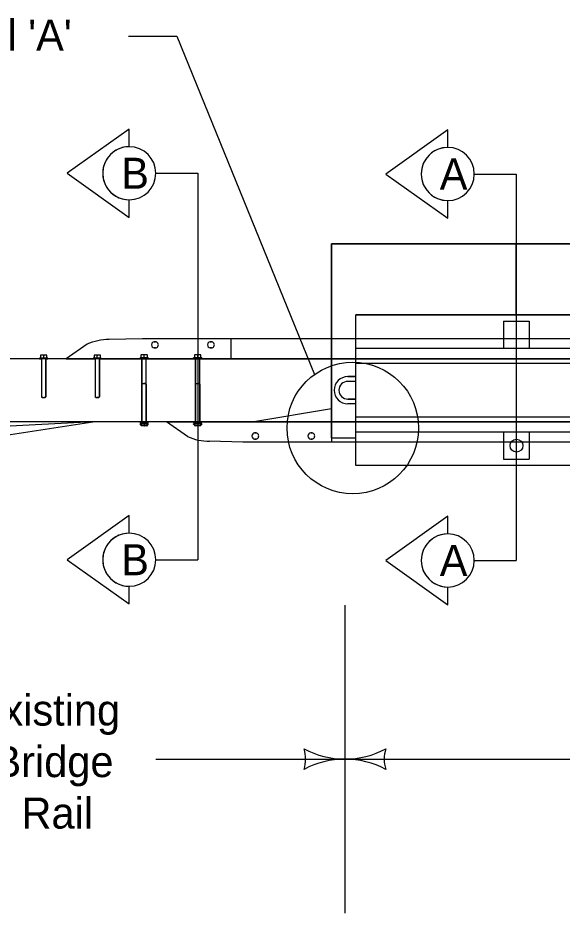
# Model space of a CAD drawing. Extents: x 10028 to 81668, y 3581 to 11018.
# Drawn here: x 21204 to 21470.5, y 8503.4 to 8941.5 of the extents above; entities that cross this region are included whole.
import ezdxf

# ---------------------------------------------------------------- set-up
doc = ezdxf.new("R2010")
doc.units = 0
for name, color, linetype in [('conPaving', 7, 'Continuous'), ('dsnCellsNorthArrow', 7, 'Continuous'), ('dsnTextTabulation', 7, 'Continuous'), ('Level 41', 7, 'Continuous'), ('Level 9', 7, 'Continuous')]:
    doc.layers.add(name, color=color, linetype=linetype)

msp = doc.modelspace()

# ---------------------------------------------------------------- linework, layer by layer
at = {"layer": 'conPaving'}
for p, q in [((21448.05, 8831.02), (21357.59, 8831.02)), ((21357.59, 8831.02), (21357.59, 8736.05)), ((21448.05, 8796.14), (21448.05, 8831.02)), ((21369.47, 8796.14), (21448.05, 8796.14)), ((21237.88, 8781.76), (21227.62, 8774.62)), ((21265.03, 8784.52), (21248.71, 8784.09)), ((21550.11, 8784.52), (21265.03, 8784.52)), ((21270.79, 8782.98), (21271.46, 8782.98)), ((21298.21, 8782.98), (21298.88, 8782.98)), ((21216.98, 8776.48), (21215.38, 8776.48)), ((21218, 8776.48), (21216.98, 8776.48)), ((21264.25, 8776.37), (21264.25, 8775.11)), ((21266.13, 8776.68), (21264.54, 8776.68)), ((21267.15, 8776.68), (21266.13, 8776.68)), ((21267.44, 8775.11), (21267.44, 8776.37)), ((21271.46, 8780.01), (21270.79, 8780.01)), ((21290.47, 8776.37), (21290.47, 8775.11)), ((21292.34, 8776.68), (21290.75, 8776.68)), ((21293.37, 8776.68), (21292.34, 8776.68)), ((21293.65, 8775.11), (21293.65, 8776.37)), ((21298.88, 8780.01), (21298.21, 8780.01)), ((21215.1, 8774.91), (21214.7, 8774.91)), ((21214.7, 8774.91), (21214.7, 8774.62)), ((21214.7, 8774.62), (21215.63, 8774.62)), ((21215.1, 8776.17), (21215.1, 8774.91)), ((21215.63, 8774.62), (21215.63, 8756.13)), ((21217.75, 8756.13), (21217.75, 8774.62)), ((21217.75, 8774.62), (21218.68, 8774.62)), ((21218.29, 8774.91), (21218.29, 8776.17)), ((21218.68, 8774.91), (21218.29, 8774.91)), ((21218.68, 8774.62), (21218.68, 8774.91)), ((21227.62, 8774.62), (21241.85, 8774.62)), ((21241.85, 8774.62), (21241.85, 8756.13)), ((21243.97, 8756.13), (21243.97, 8774.62)), ((21243.97, 8774.62), (21571.16, 8774.62)), ((21264.25, 8775.11), (21263.85, 8775.11)), ((21263.85, 8775.11), (21263.85, 8774.81)), ((21263.85, 8774.81), (21264.78, 8774.81)), ((21264.78, 8774.81), (21264.78, 8742.89)), ((21266.91, 8742.89), (21266.91, 8774.81)), ((21266.91, 8774.81), (21267.84, 8774.81)), ((21267.84, 8775.11), (21267.44, 8775.11)), ((21267.84, 8774.81), (21267.84, 8775.11)), ((21290.47, 8775.11), (21290.07, 8775.11)), ((21290.07, 8775.11), (21290.07, 8774.81)), ((21290.07, 8774.81), (21291, 8774.81)), ((21291, 8774.81), (21291, 8742.89)), ((21293.12, 8742.89), (21293.12, 8774.81)), ((21293.12, 8774.81), (21294.05, 8774.81)), ((21294.05, 8775.11), (21293.65, 8775.11)), ((21294.05, 8774.81), (21294.05, 8775.11)), ((21365.54, 8765.96), (21369.47, 8765.96)), ((21264.78, 8762.26), (21265.31, 8762.65)), ((21264.78, 8743.77), (21264.78, 8762.26)), ((21265.31, 8762.65), (21265.84, 8762.65)), ((21265.84, 8762.65), (21266.38, 8762.65)), ((21266.38, 8762.65), (21266.91, 8762.26)), ((21266.91, 8762.26), (21266.91, 8743.77)), ((21291, 8762.26), (21291.53, 8762.65)), ((21291, 8743.77), (21291, 8762.26)), ((21291.53, 8762.65), (21292.06, 8762.65)), ((21292.06, 8762.65), (21292.59, 8762.65)), ((21292.59, 8762.65), (21293.12, 8762.26)), ((21293.12, 8762.26), (21293.12, 8743.77)), ((21215.63, 8756.13), (21216.16, 8755.74)), ((21216.16, 8755.74), (21216.69, 8755.74)), ((21216.69, 8755.74), (21217.22, 8755.74)), ((21217.22, 8755.74), (21217.75, 8756.13)), ((21241.85, 8756.13), (21242.38, 8755.74)), ((21242.38, 8755.74), (21242.91, 8755.74)), ((21242.91, 8755.74), (21243.44, 8755.74)), ((21243.44, 8755.74), (21243.97, 8756.13)), ((21369.47, 8752.59), (21365.54, 8752.59)), ((21263.85, 8743.48), (21263.85, 8743.77)), ((21263.85, 8743.77), (21264.78, 8743.77)), ((21264.25, 8743.48), (21263.85, 8743.48)), ((21264.25, 8742.22), (21264.25, 8743.48)), ((21266.13, 8741.91), (21264.54, 8741.91)), ((21264.78, 8742.89), (21266.91, 8742.89)), ((21267.15, 8741.91), (21266.13, 8741.91)), ((21266.91, 8743.77), (21267.84, 8743.77)), ((21267.84, 8743.48), (21267.44, 8743.48)), ((21267.44, 8743.48), (21267.44, 8742.22)), ((21267.84, 8743.77), (21267.84, 8743.48)), ((21287.03, 8736.63), (21276.78, 8743.77)), ((21276.78, 8743.77), (21291, 8743.77)), ((21291, 8742.89), (21293.12, 8742.89)), ((21293.12, 8743.77), (21620.32, 8743.77)), ((21320.61, 8738.38), (21319.94, 8738.38)), ((21348.03, 8738.38), (21347.37, 8738.38)), ((21314.18, 8733.87), (21297.86, 8734.3)), ((21599.26, 8733.87), (21314.18, 8733.87)), ((21319.94, 8735.41), (21320.61, 8735.41)), ((21347.37, 8735.41), (21348.03, 8735.41)), ((21357.59, 8736.05), (21369.47, 8736.05))]:
    msp.add_line(p, q, dxfattribs=at)
for points in [[(21369.47, 8765.96), (21369.47, 8772.38), (21369.47, 8779.76), (21369.47, 8796.14)], [(21369.47, 8736.05), (21369.47, 8738.8), (21369.47, 8746.17), (21369.47, 8752.59)]]:
    msp.add_lwpolyline(points, dxfattribs=at)
for centre, radius, start, end in [((21365.54, 8759.28), 6.68, 90, 270), ((21265.84, 8745.29), 3.35, 233.5244, 306.4756), ((21292.06, 8745.29), 3.35, 233.5244, 306.4756)]:
    msp.add_arc(centre, radius, start, end, dxfattribs=at)
for centre, major_axis, ratio, start_param, end_param in [((21248.71, 8758.56), (-25.97, 0), 0.98332, 4.712389, 5.142831), ((21270.79, 8781.5), (0, -1.49), 0.899999, 3.141593, 6.283185), ((21271.46, 8781.5), (0, -1.49), 0.899999, 0, 3.141593), ((21298.21, 8781.5), (0, -1.49), 0.899999, 3.141593, 6.283185), ((21298.88, 8781.5), (0, -1.49), 0.899999, 0, 3.141593), ((21215.38, 8776.17), (0, -0.315), 0.899999, 3.141593, 4.712389), ((21218, 8776.17), (0, -0.315), 0.899999, 1.570796, 3.141593), ((21264.54, 8776.37), (0, -0.315), 0.899999, 3.141593, 4.712389), ((21267.15, 8776.37), (0, -0.315), 0.899999, 1.570796, 3.141593), ((21290.75, 8776.37), (0, -0.315), 0.899999, 3.141593, 4.712389), ((21293.37, 8776.37), (0, -0.315), 0.899999, 1.570796, 3.141593), ((21264.54, 8742.22), (0, -0.315), 0.899999, 4.712389, 6.283185), ((21267.15, 8742.22), (0, -0.315), 0.899999, 6.283185, 7.853982), ((21319.94, 8736.89), (0, -1.49), 0.899999, 3.141593, 6.283185), ((21320.61, 8736.89), (0, -1.49), 0.899999, 0, 3.141593), ((21347.37, 8736.89), (0, -1.49), 0.899999, 3.141593, 6.283185), ((21348.03, 8736.89), (0, -1.49), 0.899999, 0, 3.141593), ((21297.86, 8759.83), (-25.97, 0), 0.98332, 1.140354, 1.570796)]:
    msp.add_ellipse(centre, major_axis=major_axis, ratio=ratio, start_param=start_param, end_param=end_param, dxfattribs=at)
at = {"layer": 'dsnCellsNorthArrow'}
for p, q in [((21258.56, 8887.14), (21228.22, 8865.47)), ((21258.56, 8878.47), (21258.56, 8887.14)), ((21414.48, 8886.78), (21384.15, 8865.12)), ((21414.48, 8878.12), (21414.48, 8886.78)), ((21228.22, 8865.47), (21258.56, 8843.8)), ((21384.15, 8865.12), (21414.48, 8843.45)), ((21258.56, 8843.8), (21258.56, 8852.47)), ((21414.48, 8843.45), (21414.48, 8852.12)), ((21357.59, 8774.6), (21082.34, 8774.63)), ((21357.59, 8750.27), (21357.59, 8774.6)), ((21318.62, 8743.77), (21357.59, 8750.27)), ((21240.67, 8743.77), (21082.34, 8743.78)), ((21240.67, 8743.77), (21082.34, 8735.66)), ((21082.34, 8719.43), (21240.67, 8743.77)), ((21318.62, 8743.77), (21240.67, 8743.77)), ((21258.56, 8697.99), (21228.22, 8676.33)), ((21258.56, 8689.33), (21258.56, 8697.99)), ((21414.48, 8697.64), (21384.15, 8675.97)), ((21414.48, 8688.97), (21414.48, 8697.64)), ((21228.22, 8676.33), (21258.56, 8654.66)), ((21384.15, 8675.97), (21414.48, 8654.31)), ((21258.56, 8654.66), (21258.56, 8663.32)), ((21414.48, 8654.31), (21414.48, 8662.97))]:
    msp.add_line(p, q, dxfattribs=at)
for centre, start, end in [((21258.56, 8865.47), 89.9948, 270.0052), ((21258.56, 8865.47), 90.0052, 269.9948), ((21258.56, 8865.47), 270.0052, 89.9948), ((21414.48, 8865.12), 89.9948, 270.0052), ((21414.49, 8865.12), 90.0052, 269.9948), ((21414.48, 8865.12), 270.0052, 89.9948), ((21258.56, 8676.32), 89.9948, 270.0052), ((21258.56, 8676.32), 90.0052, 269.9948), ((21258.56, 8676.32), 270.0052, 89.9948), ((21414.48, 8675.97), 89.9948, 270.0052), ((21414.49, 8675.97), 90.0052, 269.9948), ((21414.48, 8675.97), 270.0052, 89.9948)]:
    msp.add_arc(centre, 13, start, end, dxfattribs=at)
at = {"layer": 'dsnTextTabulation'}
for p, q in [((21258.18, 8932.58), (21281.78, 8932.58)), ((21281.78, 8932.58), (21349.26, 8767.02)), ((21271.56, 8865.47), (21292.12, 8865.47)), ((21292.12, 8865.47), (21292.12, 8676.32)), ((21427.48, 8865.12), (21448.05, 8865.12)), ((21448.05, 8865.12), (21448.05, 8675.97)), ((21860.99, 8796.14), (21369.47, 8796.14)), ((21369.47, 8722.41), (21369.47, 8796.14)), ((21860.99, 8779.76), (21369.47, 8779.76)), ((21860.99, 8772.38), (21369.47, 8772.38)), ((21860.99, 8746.17), (21369.47, 8746.17)), ((21860.99, 8738.8), (21369.47, 8738.8)), ((21860.99, 8722.41), (21369.47, 8722.41)), ((21271.56, 8676.32), (21292.12, 8676.32)), ((21427.48, 8675.97), (21448.05, 8675.97)), ((21364.12, 8654.09), (21364.12, 8503.37)), ((21271.5, 8578.73), (21364.12, 8578.73)), ((21364.12, 8578.73), (21619.77, 8578.73))]:
    msp.add_line(p, q, dxfattribs=at)
for centre, radius, start, end in [((21328.48, 8578.73), 16.42, 342.2667, 17.7334), ((21364.12, 8621.23), 42.5, 241.9275, 270), ((21364.12, 8621.23), 42.5, 270, 298.0725), ((21399.75, 8578.73), 16.42, 162.2666, 197.7334), ((21364.12, 8536.23), 42.5, 90, 118.0725), ((21364.12, 8536.23), 42.5, 61.9275, 90)]:
    msp.add_arc(centre, radius, start, end, dxfattribs=at)
at = {"layer": 'Level 41'}
for p, q in [((21441.82, 8793.02), (21454.4, 8793.02)), ((21441.82, 8793.02), (21441.82, 8779.76)), ((21454.4, 8793.02), (21454.4, 8779.76)), ((21369.47, 8765.96), (21365.54, 8765.96)), ((21369.47, 8763.6), (21365.54, 8763.6)), ((21369.47, 8754.95), (21365.54, 8754.95)), ((21369.47, 8752.59), (21365.54, 8752.59)), ((21441.82, 8738.8), (21441.82, 8725.54)), ((21454.4, 8738.8), (21454.4, 8725.54)), ((21441.82, 8725.54), (21454.4, 8725.54))]:
    msp.add_line(p, q, dxfattribs=at)
msp.add_circle((21448.11, 8732.17), 3.15, dxfattribs=at)
for radius in [6.68, 4.33]:
    msp.add_arc((21365.54, 8759.28), radius, 90, 270, dxfattribs=at)
at = {"layer": 'Level 9'}
for p, q in [((21357.59, 8736.05), (21357.59, 8831.02)), ((21357.59, 8831.02), (23377.13, 8831.02)), ((21857.99, 8831.02), (21448.05, 8831.02)), ((21448.05, 8831.02), (21448.05, 8796.14)), ((21448.05, 8796.14), (21860.99, 8796.14)), ((21550.11, 8784.52), (21265.03, 8784.52)), ((21308.44, 8774.62), (21308.44, 8784.52)), ((21216.98, 8776.48), (21215.38, 8776.48)), ((21218, 8776.48), (21216.98, 8776.48)), ((21243.19, 8776.48), (21241.6, 8776.48)), ((21244.22, 8776.48), (21243.19, 8776.48)), ((21264.25, 8776.37), (21264.25, 8775.11)), ((21266.13, 8776.68), (21264.54, 8776.68)), ((21265.84, 8775.11), (21265.84, 8776.37)), ((21267.15, 8776.68), (21266.13, 8776.68)), ((21267.44, 8775.11), (21267.44, 8776.37)), ((21290.47, 8776.37), (21290.47, 8775.11)), ((21292.34, 8776.68), (21290.75, 8776.68)), ((21292.06, 8775.11), (21292.06, 8776.37)), ((21293.37, 8776.68), (21292.34, 8776.68)), ((21293.65, 8775.11), (21293.65, 8776.37)), ((21604.99, 8774.62), (21210.14, 8774.62)), ((21216.69, 8774.91), (21214.7, 8774.91)), ((21214.7, 8774.62), (21214.7, 8774.91)), ((21218.68, 8774.62), (21214.7, 8774.62)), ((21215.1, 8776.17), (21215.1, 8774.91)), ((21218.29, 8774.91), (21215.1, 8774.91)), ((21216.69, 8774.62), (21215.63, 8774.62)), ((21215.63, 8774.62), (21215.63, 8756.13)), ((21216.69, 8774.91), (21216.69, 8776.17)), ((21216.69, 8774.91), (21218.68, 8774.91)), ((21217.75, 8774.62), (21217.75, 8756.13)), ((21218.29, 8774.91), (21218.29, 8776.17)), ((21218.68, 8774.91), (21218.68, 8774.62)), ((21242.91, 8774.91), (21240.92, 8774.91)), ((21240.92, 8774.62), (21240.92, 8774.91)), ((21244.9, 8774.62), (21240.92, 8774.62)), ((21241.31, 8776.17), (21241.31, 8774.91)), ((21244.5, 8774.91), (21241.31, 8774.91)), ((21242.91, 8774.62), (21241.85, 8774.62)), ((21241.85, 8774.62), (21241.85, 8756.13)), ((21242.91, 8774.91), (21242.91, 8776.17)), ((21242.91, 8774.91), (21244.9, 8774.91)), ((21243.97, 8774.62), (21243.97, 8756.13)), ((21244.5, 8774.91), (21244.5, 8776.17)), ((21244.9, 8774.91), (21244.9, 8774.62)), ((21265.84, 8775.11), (21263.85, 8775.11)), ((21263.85, 8774.81), (21263.85, 8775.11)), ((21267.84, 8774.81), (21263.85, 8774.81)), ((21267.44, 8775.11), (21264.25, 8775.11)), ((21265.84, 8774.81), (21264.78, 8774.81)), ((21264.78, 8742.89), (21264.78, 8774.81)), ((21265.84, 8775.11), (21267.84, 8775.11)), ((21266.91, 8742.89), (21266.91, 8774.81)), ((21267.84, 8775.11), (21267.84, 8774.81)), ((21292.06, 8775.11), (21290.07, 8775.11)), ((21290.07, 8774.81), (21290.07, 8775.11)), ((21294.05, 8774.81), (21290.07, 8774.81)), ((21293.65, 8775.11), (21290.47, 8775.11)), ((21292.06, 8774.81), (21291, 8774.81)), ((21291, 8742.89), (21291, 8774.81)), ((21292.06, 8775.11), (21294.05, 8775.11)), ((21293.12, 8742.89), (21293.12, 8774.81)), ((21294.05, 8775.11), (21294.05, 8774.81)), ((21369.47, 8763.6), (21365.54, 8763.6)), ((21369.47, 8754.95), (21369.47, 8763.6)), ((21265.31, 8762.65), (21264.78, 8762.26)), ((21264.78, 8743.77), (21264.78, 8762.26)), ((21265.31, 8762.65), (21265.84, 8762.65)), ((21266.38, 8762.65), (21265.84, 8762.65)), ((21266.38, 8762.65), (21266.91, 8762.26)), ((21266.91, 8743.77), (21266.91, 8762.26)), ((21291.53, 8762.65), (21291, 8762.26)), ((21291, 8743.77), (21291, 8762.26)), ((21291.53, 8762.65), (21292.06, 8762.65)), ((21292.59, 8762.65), (21292.06, 8762.65)), ((21292.59, 8762.65), (21293.12, 8762.26)), ((21293.12, 8743.77), (21293.12, 8762.26)), ((21216.16, 8755.74), (21215.63, 8756.13)), ((21216.16, 8755.74), (21216.69, 8755.74)), ((21217.22, 8755.74), (21216.69, 8755.74)), ((21217.22, 8755.74), (21217.75, 8756.13)), ((21242.38, 8755.74), (21241.85, 8756.13)), ((21242.38, 8755.74), (21242.91, 8755.74)), ((21243.44, 8755.74), (21242.91, 8755.74)), ((21243.44, 8755.74), (21243.97, 8756.13)), ((21365.54, 8754.95), (21369.47, 8754.95)), ((21654.15, 8743.77), (21259.29, 8743.77)), ((21267.84, 8743.77), (21263.85, 8743.77)), ((21263.85, 8743.77), (21263.85, 8743.48)), ((21265.84, 8743.48), (21263.85, 8743.48)), ((21265.84, 8742.89), (21263.85, 8742.89)), ((21263.85, 8742.6), (21263.85, 8742.89)), ((21267.84, 8742.6), (21263.85, 8742.6)), ((21267.44, 8743.48), (21264.25, 8743.48)), ((21264.25, 8742.22), (21264.25, 8743.48)), ((21267.44, 8742.89), (21264.25, 8742.89)), ((21266.13, 8741.91), (21264.54, 8741.91)), ((21265.84, 8743.77), (21264.78, 8743.77)), ((21265.84, 8742.6), (21264.78, 8742.6)), ((21265.84, 8743.48), (21267.84, 8743.48)), ((21265.84, 8743.48), (21265.84, 8742.22)), ((21265.84, 8742.89), (21267.84, 8742.89)), ((21267.15, 8741.91), (21266.13, 8741.91)), ((21267.44, 8743.48), (21267.44, 8742.22)), ((21267.84, 8743.48), (21267.84, 8743.77)), ((21267.84, 8742.89), (21267.84, 8742.6)), ((21294.05, 8743.77), (21290.07, 8743.77)), ((21290.07, 8743.77), (21290.07, 8743.48)), ((21292.06, 8743.48), (21290.07, 8743.48)), ((21292.06, 8742.89), (21290.07, 8742.89)), ((21290.07, 8742.6), (21290.07, 8742.89)), ((21294.05, 8742.6), (21290.07, 8742.6)), ((21293.65, 8743.48), (21290.47, 8743.48)), ((21290.47, 8742.22), (21290.47, 8743.48)), ((21293.65, 8742.89), (21290.47, 8742.89)), ((21292.34, 8741.91), (21290.75, 8741.91)), ((21292.06, 8743.77), (21291, 8743.77)), ((21292.06, 8742.6), (21291, 8742.6)), ((21292.06, 8743.48), (21294.05, 8743.48)), ((21292.06, 8743.48), (21292.06, 8742.22)), ((21292.06, 8742.89), (21294.05, 8742.89)), ((21293.37, 8741.91), (21292.34, 8741.91)), ((21293.65, 8743.48), (21293.65, 8742.22)), ((21294.05, 8743.48), (21294.05, 8743.77)), ((21294.05, 8742.89), (21294.05, 8742.6)), ((21357.6, 8743.77), (21357.6, 8733.87)), ((21599.26, 8733.87), (21314.18, 8733.87)), ((21357.59, 8736.05), (21369.47, 8736.05))]:
    msp.add_line(p, q, dxfattribs=at)
for points in [[(21237.88, 8781.76), (21227.62, 8774.62)], [(21265.03, 8784.52), (21248.71, 8784.09)], [(21271.46, 8782.98), (21270.79, 8782.98)], [(21298.88, 8782.98), (21298.21, 8782.98)], [(21270.79, 8780.01), (21271.46, 8780.01)], [(21298.21, 8780.01), (21298.88, 8780.01)], [(21287.03, 8736.63), (21276.78, 8743.77)], [(21319.94, 8738.38), (21320.61, 8738.38)], [(21347.37, 8738.38), (21348.03, 8738.38)], [(21314.18, 8733.87), (21297.86, 8734.3)], [(21320.61, 8735.41), (21319.94, 8735.41)], [(21348.03, 8735.41), (21347.37, 8735.41)]]:
    msp.add_lwpolyline(points, dxfattribs=at)
msp.add_circle((21368, 8740.82), 32.2, dxfattribs=at)
msp.add_arc((21365.54, 8759.28), 4.33, 90, 270, dxfattribs=at)
for centre, major_axis, ratio, start_param, end_param in [((21248.71, 8758.56), (-25.97, 0), 0.98332, 4.712389, 5.142831), ((21270.79, 8781.5), (0, -1.49), 0.899999, 3.141593, 6.283185), ((21271.46, 8781.5), (0, -1.49), 0.899999, 0, 3.141593), ((21298.21, 8781.5), (0, -1.49), 0.899999, 3.141593, 6.283185), ((21298.88, 8781.5), (0, -1.49), 0.899999, 0, 3.141593), ((21215.38, 8776.17), (0, -0.315), 0.899999, 3.141593, 4.712389), ((21216.41, 8776.17), (0, -0.315), 0.899999, 1.570796, 3.141593), ((21216.98, 8776.17), (0, -0.315), 0.899999, 3.141593, 4.712389), ((21218, 8776.17), (0, -0.315), 0.899999, 1.570796, 3.141593), ((21241.6, 8776.17), (0, -0.315), 0.899999, 3.141593, 4.712389), ((21242.62, 8776.17), (0, -0.315), 0.899999, 1.570796, 3.141593), ((21243.19, 8776.17), (0, -0.315), 0.899999, 3.141593, 4.712389), ((21244.22, 8776.17), (0, -0.315), 0.899999, 1.570796, 3.141593), ((21264.54, 8776.37), (0, -0.315), 0.899999, 3.141593, 4.712389), ((21265.56, 8776.37), (0, -0.315), 0.899999, 1.570796, 3.141593), ((21266.13, 8776.37), (0, -0.315), 0.899999, 3.141593, 4.712389), ((21267.15, 8776.37), (0, -0.315), 0.899999, 1.570796, 3.141593), ((21290.75, 8776.37), (0, -0.315), 0.899999, 3.141593, 4.712389), ((21291.78, 8776.37), (0, -0.315), 0.899999, 1.570796, 3.141593), ((21292.34, 8776.37), (0, -0.315), 0.899999, 3.141593, 4.712389), ((21293.37, 8776.37), (0, -0.315), 0.899999, 1.570796, 3.141593), ((21264.54, 8742.22), (0, -0.315), 0.899999, 4.712389, 6.283185), ((21265.56, 8742.22), (0, -0.315), 0.899999, 0, 1.570796), ((21266.13, 8742.22), (0, -0.315), 0.899999, 4.712389, 6.283185), ((21267.15, 8742.22), (0, -0.315), 0.899999, 6.283185, 7.853982), ((21290.75, 8742.22), (0, -0.315), 0.899999, 4.712389, 6.283185), ((21291.78, 8742.22), (0, -0.315), 0.899999, 0, 1.570796), ((21292.34, 8742.22), (0, -0.315), 0.899999, 4.712389, 6.283185), ((21293.37, 8742.22), (0, -0.315), 0.899999, 6.283185, 7.853982), ((21319.94, 8736.89), (0, -1.49), 0.899999, 3.141593, 6.283185), ((21320.61, 8736.89), (0, -1.49), 0.899999, 0, 3.141593), ((21347.37, 8736.89), (0, -1.49), 0.899999, 3.141593, 6.283185), ((21348.03, 8736.89), (0, -1.49), 0.899999, 0, 3.141593), ((21297.86, 8759.83), (-25.97, 0), 0.98332, 1.140354, 1.570796)]:
    msp.add_ellipse(centre, major_axis=major_axis, ratio=ratio, start_param=start_param, end_param=end_param, dxfattribs=at)

# ---------------------------------------------------------------- texts
at = {"layer": 'dsnCellsNorthArrow'}
for s, p in [("See Detail 'A'", (21109.66, 8925.51)), ('B', (21254.63, 8857.87)), ('A', (21410.56, 8857.52)), ('B', (21254.63, 8668.72)), ('A', (21410.56, 8668.37)), ('Existing', (21182.93, 8595.13)), ('Bridge', (21192.09, 8569.93)), ('Rail', (21205.8, 8544.73))]:
    msp.add_text(s, height=15.2, dxfattribs=at).set_placement(p)

doc.saveas('drawing.dxf')
